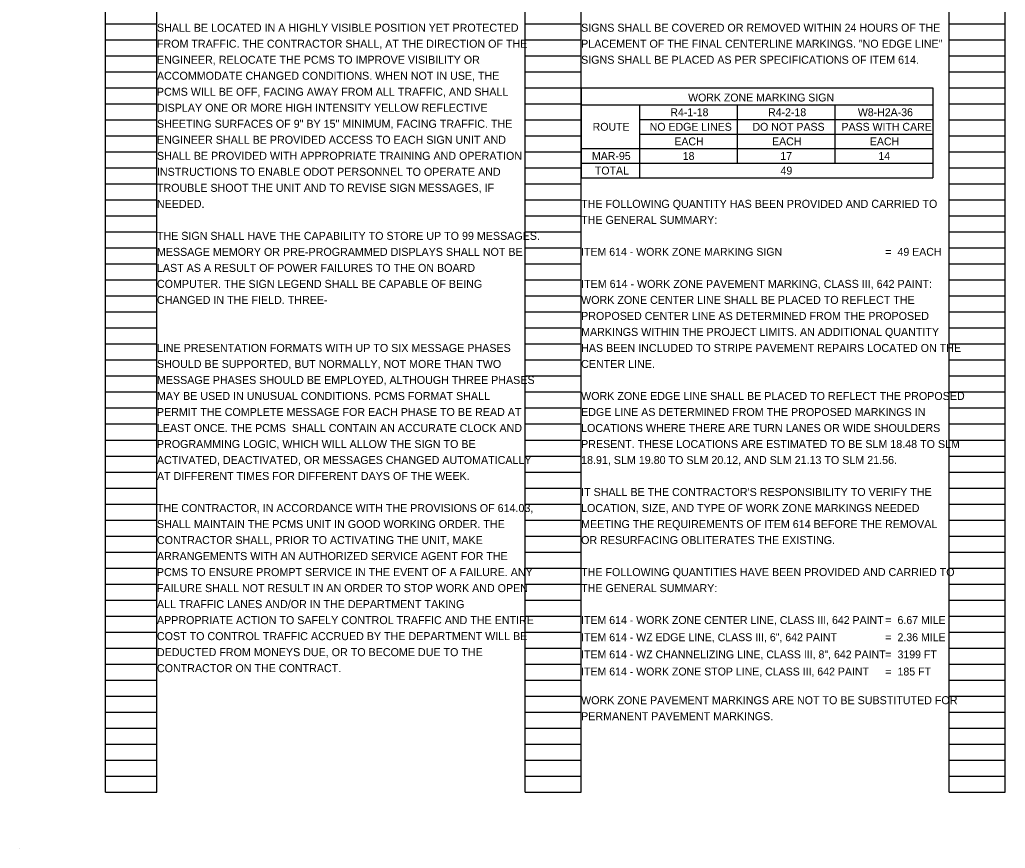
# Model space of a CAD drawing. Extents: x -23 to 32, y -58.1 to 21.1.
# Drawn here: x 0 to 17.24, y -58.15 to -43.65 of the extents above; entities that cross this region are included whole.
import ezdxf

# ---------------------------------------------------------------- set-up
doc = ezdxf.new("R2010")
doc.units = 0
for name, color, linetype in [('Default', 7, 'Continuous'), ('SH_Data', 7, 'Continuous'), ('SH_Text', 7, 'Continuous')]:
    doc.layers.add(name, color=color, linetype=linetype)

msp = doc.modelspace()

# ---------------------------------------------------------------- linework, layer by layer
at = {"layer": 'Default'}
for p, q in [((9.82, -44.845), (15.97, -44.845)), ((9.82, -44.845), (9.82, -46.42)), ((15.97, -44.845), (15.97, -46.42)), ((9.82, -45.145), (15.97, -45.145)), ((10.84, -45.145), (10.84, -46.42)), ((12.55, -45.145), (12.55, -46.165)), ((14.26, -45.145), (14.26, -46.165)), ((10.84, -45.4), (15.97, -45.4)), ((10.84, -45.655), (15.97, -45.655)), ((9.82, -45.91), (15.97, -45.91)), ((9.82, -46.165), (15.97, -46.165)), ((9.82, -46.42), (15.97, -46.42))]:
    msp.add_line(p, q, dxfattribs=at)
at = {"layer": 'SH_Data'}
for p, q in [((1.5, -57.165), (1.5, -37.005)), ((2.4, -57.165), (2.4, -37.005)), ((8.84, -57.165), (8.84, -37.005)), ((9.82, -57.165), (9.82, -37.005)), ((16.26, -57.165), (16.26, -37.005)), ((17.24, -57.165), (17.24, -37.005)), ((1.5, -43.725), (2.4, -43.725)), ((8.84, -43.725), (9.82, -43.725)), ((16.26, -43.725), (17.24, -43.725)), ((1.5, -44.005), (2.4, -44.005)), ((8.84, -44.005), (9.82, -44.005)), ((16.26, -44.005), (17.24, -44.005)), ((1.5, -44.285), (2.4, -44.285)), ((8.84, -44.285), (9.82, -44.285)), ((16.26, -44.285), (17.24, -44.285)), ((1.5, -44.565), (2.4, -44.565)), ((8.84, -44.565), (9.82, -44.565)), ((16.26, -44.565), (17.24, -44.565)), ((1.5, -44.845), (2.4, -44.845)), ((8.84, -44.845), (9.82, -44.845)), ((16.26, -44.845), (17.24, -44.845)), ((1.5, -45.125), (2.4, -45.125)), ((8.84, -45.125), (9.82, -45.125)), ((16.26, -45.125), (17.24, -45.125)), ((1.5, -45.405), (2.4, -45.405)), ((8.84, -45.405), (9.82, -45.405)), ((16.26, -45.405), (17.24, -45.405)), ((1.5, -45.685), (2.4, -45.685)), ((8.84, -45.685), (9.82, -45.685)), ((16.26, -45.685), (17.24, -45.685)), ((1.5, -45.965), (2.4, -45.965)), ((8.84, -45.965), (9.82, -45.965)), ((16.26, -45.965), (17.24, -45.965)), ((1.5, -46.245), (2.4, -46.245)), ((8.84, -46.245), (9.82, -46.245)), ((16.26, -46.245), (17.24, -46.245)), ((1.5, -46.525), (2.4, -46.525)), ((8.84, -46.525), (9.82, -46.525)), ((16.26, -46.525), (17.24, -46.525)), ((1.5, -46.805), (2.4, -46.805)), ((8.84, -46.805), (9.82, -46.805)), ((16.26, -46.805), (17.24, -46.805)), ((1.5, -47.085), (2.4, -47.085)), ((8.84, -47.085), (9.82, -47.085)), ((16.26, -47.085), (17.24, -47.085)), ((1.5, -47.365), (2.4, -47.365)), ((8.84, -47.365), (9.82, -47.365)), ((16.26, -47.365), (17.24, -47.365)), ((1.5, -47.645), (2.4, -47.645)), ((8.84, -47.645), (9.82, -47.645)), ((16.26, -47.645), (17.24, -47.645)), ((1.5, -47.925), (2.4, -47.925)), ((8.84, -47.925), (9.82, -47.925)), ((16.26, -47.925), (17.24, -47.925)), ((1.5, -48.205), (2.4, -48.205)), ((8.84, -48.205), (9.82, -48.205)), ((16.26, -48.205), (17.24, -48.205)), ((1.5, -48.485), (2.4, -48.485)), ((8.84, -48.485), (9.82, -48.485)), ((16.26, -48.485), (17.24, -48.485)), ((1.5, -48.765), (2.4, -48.765)), ((8.84, -48.765), (9.82, -48.765)), ((16.26, -48.765), (17.24, -48.765)), ((1.5, -49.045), (2.4, -49.045)), ((8.84, -49.045), (9.82, -49.045)), ((16.26, -49.045), (17.24, -49.045)), ((1.5, -49.325), (2.4, -49.325)), ((8.84, -49.325), (9.82, -49.325)), ((16.26, -49.325), (17.24, -49.325)), ((1.5, -49.605), (2.4, -49.605)), ((8.84, -49.605), (9.82, -49.605)), ((16.26, -49.605), (17.24, -49.605)), ((1.5, -49.885), (2.4, -49.885)), ((8.84, -49.885), (9.82, -49.885)), ((16.26, -49.885), (17.24, -49.885)), ((1.5, -50.165), (2.4, -50.165)), ((8.84, -50.165), (9.82, -50.165)), ((16.26, -50.165), (17.24, -50.165)), ((1.5, -50.445), (2.4, -50.445)), ((8.84, -50.445), (9.82, -50.445)), ((16.26, -50.445), (17.24, -50.445)), ((1.5, -50.725), (2.4, -50.725)), ((8.84, -50.725), (9.82, -50.725)), ((16.26, -50.725), (17.24, -50.725)), ((1.5, -51.005), (2.4, -51.005)), ((8.84, -51.005), (9.82, -51.005)), ((16.26, -51.005), (17.24, -51.005)), ((1.5, -51.285), (2.4, -51.285)), ((8.84, -51.285), (9.82, -51.285)), ((16.26, -51.285), (17.24, -51.285)), ((1.5, -51.565), (2.4, -51.565)), ((8.84, -51.565), (9.82, -51.565)), ((16.26, -51.565), (17.24, -51.565)), ((1.5, -51.845), (2.4, -51.845)), ((8.84, -51.845), (9.82, -51.845)), ((16.26, -51.845), (17.24, -51.845)), ((1.5, -52.125), (2.4, -52.125)), ((8.84, -52.125), (9.82, -52.125)), ((16.26, -52.125), (17.24, -52.125)), ((1.5, -52.405), (2.4, -52.405)), ((8.84, -52.405), (9.82, -52.405)), ((16.26, -52.405), (17.24, -52.405)), ((1.5, -52.685), (2.4, -52.685)), ((8.84, -52.685), (9.82, -52.685)), ((16.26, -52.685), (17.24, -52.685)), ((1.5, -52.965), (2.4, -52.965)), ((8.84, -52.965), (9.82, -52.965)), ((16.26, -52.965), (17.24, -52.965)), ((1.5, -53.245), (2.4, -53.245)), ((8.84, -53.245), (9.82, -53.245)), ((16.26, -53.245), (17.24, -53.245)), ((1.5, -53.525), (2.4, -53.525)), ((8.84, -53.525), (9.82, -53.525)), ((16.26, -53.525), (17.24, -53.525)), ((1.5, -53.805), (2.4, -53.805)), ((8.84, -53.805), (9.82, -53.805)), ((16.26, -53.805), (17.24, -53.805)), ((1.5, -54.085), (2.4, -54.085)), ((8.84, -54.085), (9.82, -54.085)), ((16.26, -54.085), (17.24, -54.085)), ((1.5, -54.365), (2.4, -54.365)), ((8.84, -54.365), (9.82, -54.365)), ((16.26, -54.365), (17.24, -54.365)), ((1.5, -54.645), (2.4, -54.645)), ((8.84, -54.645), (9.82, -54.645)), ((16.26, -54.645), (17.24, -54.645)), ((1.5, -54.925), (2.4, -54.925)), ((8.84, -54.925), (9.82, -54.925)), ((16.26, -54.925), (17.24, -54.925)), ((1.5, -55.205), (2.4, -55.205)), ((8.84, -55.205), (9.82, -55.205)), ((16.26, -55.205), (17.24, -55.205)), ((1.5, -55.485), (2.4, -55.485)), ((8.84, -55.485), (9.82, -55.485)), ((16.26, -55.485), (17.24, -55.485)), ((1.5, -55.765), (2.4, -55.765)), ((8.84, -55.765), (9.82, -55.765)), ((16.26, -55.765), (17.24, -55.765)), ((1.5, -56.045), (2.4, -56.045)), ((8.84, -56.045), (9.82, -56.045)), ((16.26, -56.045), (17.24, -56.045)), ((1.5, -56.325), (2.4, -56.325)), ((8.84, -56.325), (9.82, -56.325)), ((16.26, -56.325), (17.24, -56.325)), ((1.5, -56.605), (2.4, -56.605)), ((8.84, -56.605), (9.82, -56.605)), ((16.26, -56.605), (17.24, -56.605)), ((1.5, -56.885), (2.4, -56.885)), ((8.84, -56.885), (9.82, -56.885)), ((16.26, -56.885), (17.24, -56.885)), ((1.5, -57.165), (2.4, -57.165)), ((8.84, -57.165), (9.82, -57.165)), ((16.26, -57.165), (17.24, -57.165)), ((0, -58.145), (0, -58.145))]:
    msp.add_line(p, q, dxfattribs=at)

# ---------------------------------------------------------------- texts
at = {"layer": 'Default'}
for s, p in [('WORK ZONE MARKING SIGN', (11.692, -45.085)), ('R4-1-18', (11.381, -45.342)), ('R4-2-18', (13.091, -45.342)), ('W8-H2A-36', (14.661, -45.342)), ('ROUTE', (10.022, -45.597)), ('NO EDGE LINES', (11.02, -45.597)), ('DO NOT PASS', (12.818, -45.597)), ('PASS WITH CARE', (14.375, -45.597)), ('EACH', (11.451, -45.852)), ('EACH', (13.161, -45.852)), ('EACH', (14.871, -45.852)), ('MAR-95', (10.01, -46.107)), ('18', (11.598, -46.107)), ('17', (13.305, -46.107)), ('14', (15.02, -46.107)), ('TOTAL', (10.061, -46.362)), ('49', (13.309, -46.362)), ('ITEM 614 - WORK ZONE MARKING SIGN', (9.82, -47.783)), ('=', (15.141, -47.783)), ('49 EACH', (15.355, -47.783)), ('ITEM 614 - WORK ZONE CENTER LINE, CLASS III, 642 PAINT', (9.82, -54.223)), ('=', (15.141, -54.223)), ('6.67 MILE', (15.355, -54.223)), ('ITEM 614 - WZ EDGE LINE, CLASS III, 6", 642 PAINT', (9.82, -54.523)), ('=', (15.141, -54.523)), ('2.36 MILE', (15.355, -54.523)), ('ITEM 614 - WZ CHANNELIZING LINE, CLASS III, 8", 642 PAINT', (9.82, -54.823)), ('=', (15.141, -54.823)), ('3199 FT', (15.355, -54.823)), ('ITEM 614 - WORK ZONE STOP LINE, CLASS III, 642 PAINT', (9.82, -55.123)), ('185 FT', (15.355, -55.123)), ('=', (15.141, -55.123))]:
    msp.add_text(s, height=0.138, dxfattribs=at).set_placement(p)
at = {"layer": 'SH_Text'}
for s, p in [('SHALL BE LOCATED IN A HIGHLY VISIBLE POSITION YET PROTECTED ', (2.4, -43.865)), ('SIGNS SHALL BE COVERED OR REMOVED WITHIN 24 HOURS OF THE ', (9.82, -43.865)), ('FROM TRAFFIC. THE CONTRACTOR SHALL, AT THE DIRECTION OF THE ', (2.4, -44.145)), ('PLACEMENT OF THE FINAL CENTERLINE MARKINGS. "NO EDGE LINE" ', (9.82, -44.145)), ('ENGINEER, RELOCATE THE PCMS TO IMPROVE VISIBILITY OR ', (2.4, -44.425)), ('SIGNS SHALL BE PLACED AS PER SPECIFICATIONS OF ITEM 614.', (9.82, -44.425)), ('ACCOMMODATE CHANGED CONDITIONS. WHEN NOT IN USE, THE ', (2.4, -44.705)), ('PCMS WILL BE OFF, FACING AWAY FROM ALL TRAFFIC, AND SHALL ', (2.4, -44.985)), ('DISPLAY ONE OR MORE HIGH INTENSITY YELLOW REFLECTIVE ', (2.4, -45.265)), ('SHEETING SURFACES OF 9" BY 15" MINIMUM, FACING TRAFFIC. THE ', (2.4, -45.545)), ('ENGINEER SHALL BE PROVIDED ACCESS TO EACH SIGN UNIT AND ', (2.4, -45.825)), ('SHALL BE PROVIDED WITH APPROPRIATE TRAINING AND OPERATION ', (2.4, -46.105)), ('INSTRUCTIONS TO ENABLE ODOT PERSONNEL TO OPERATE AND ', (2.4, -46.385)), ('TROUBLE SHOOT THE UNIT AND TO REVISE SIGN MESSAGES, IF ', (2.4, -46.665)), ('NEEDED.', (2.4, -46.945)), ('THE FOLLOWING QUANTITY HAS BEEN PROVIDED AND CARRIED TO ', (9.82, -46.945)), ('THE GENERAL SUMMARY:', (9.82, -47.225)), ('THE SIGN SHALL HAVE THE CAPABILITY TO STORE UP TO 99 MESSAGES. ', (2.4, -47.505)), ('MESSAGE MEMORY OR PRE-PROGRAMMED DISPLAYS SHALL NOT BE ', (2.4, -47.785)), ('LAST AS A RESULT OF POWER FAILURES TO THE ON BOARD ', (2.4, -48.065)), ('COMPUTER. THE SIGN LEGEND SHALL BE CAPABLE OF BEING ', (2.4, -48.345)), ('ITEM 614 - WORK ZONE PAVEMENT MARKING, CLASS III, 642 PAINT:', (9.82, -48.345)), ('CHANGED IN THE FIELD. THREE-', (2.4, -48.625)), ('WORK ZONE CENTER LINE SHALL BE PLACED TO REFLECT THE ', (9.82, -48.625)), ('PROPOSED CENTER LINE AS DETERMINED FROM THE PROPOSED ', (9.82, -48.905)), ('MARKINGS WITHIN THE PROJECT LIMITS. AN ADDITIONAL QUANTITY ', (9.82, -49.185)), ('LINE PRESENTATION FORMATS WITH UP TO SIX MESSAGE PHASES ', (2.4, -49.465)), ('HAS BEEN INCLUDED TO STRIPE PAVEMENT REPAIRS LOCATED ON THE ', (9.82, -49.465)), ('SHOULD BE SUPPORTED, BUT NORMALLY, NOT MORE THAN TWO ', (2.4, -49.745)), ('CENTER LINE.', (9.82, -49.745)), ('MESSAGE PHASES SHOULD BE EMPLOYED, ALTHOUGH THREE PHASES ', (2.4, -50.025)), ('MAY BE USED IN UNUSUAL CONDITIONS. PCMS FORMAT SHALL ', (2.4, -50.305)), ('WORK ZONE EDGE LINE SHALL BE PLACED TO REFLECT THE PROPOSED ', (9.82, -50.305)), ('PERMIT THE COMPLETE MESSAGE FOR EACH PHASE TO BE READ AT ', (2.4, -50.585)), ('EDGE LINE AS DETERMINED FROM THE PROPOSED MARKINGS IN ', (9.82, -50.585)), ('LEAST ONCE. THE PCMS  SHALL CONTAIN AN ACCURATE CLOCK AND ', (2.4, -50.865)), ('LOCATIONS WHERE THERE ARE TURN LANES OR WIDE SHOULDERS ', (9.82, -50.865)), ('PROGRAMMING LOGIC, WHICH WILL ALLOW THE SIGN TO BE ', (2.4, -51.145)), ('PRESENT. THESE LOCATIONS ARE ESTIMATED TO BE SLM 18.48 TO SLM ', (9.82, -51.145)), ('ACTIVATED, DEACTIVATED, OR MESSAGES CHANGED AUTOMATICALLY ', (2.4, -51.425)), ('18.91, SLM 19.80 TO SLM 20.12, AND SLM 21.13 TO SLM 21.56.', (9.82, -51.425)), ('AT DIFFERENT TIMES FOR DIFFERENT DAYS OF THE WEEK.', (2.4, -51.705)), ("IT SHALL BE THE CONTRACTOR'S RESPONSIBILITY TO VERIFY THE ", (9.82, -51.985)), ('THE CONTRACTOR, IN ACCORDANCE WITH THE PROVISIONS OF 614.03, ', (2.4, -52.265)), ('LOCATION, SIZE, AND TYPE OF WORK ZONE MARKINGS NEEDED ', (9.82, -52.265)), ('SHALL MAINTAIN THE PCMS UNIT IN GOOD WORKING ORDER. THE ', (2.4, -52.545)), ('MEETING THE REQUIREMENTS OF ITEM 614 BEFORE THE REMOVAL ', (9.82, -52.545)), ('CONTRACTOR SHALL, PRIOR TO ACTIVATING THE UNIT, MAKE ', (2.4, -52.825)), ('OR RESURFACING OBLITERATES THE EXISTING.', (9.82, -52.825)), ('ARRANGEMENTS WITH AN AUTHORIZED SERVICE AGENT FOR THE ', (2.4, -53.105)), ('PCMS TO ENSURE PROMPT SERVICE IN THE EVENT OF A FAILURE. ANY ', (2.4, -53.385)), ('THE FOLLOWING QUANTITIES HAVE BEEN PROVIDED AND CARRIED TO ', (9.82, -53.385)), ('FAILURE SHALL NOT RESULT IN AN ORDER TO STOP WORK AND OPEN ', (2.4, -53.665)), ('THE GENERAL SUMMARY:', (9.82, -53.665)), ('ALL TRAFFIC LANES AND/OR IN THE DEPARTMENT TAKING ', (2.4, -53.945)), ('APPROPRIATE ACTION TO SAFELY CONTROL TRAFFIC AND THE ENTIRE ', (2.4, -54.225)), ('COST TO CONTROL TRAFFIC ACCRUED BY THE DEPARTMENT WILL BE ', (2.4, -54.505)), ('DEDUCTED FROM MONEYS DUE, OR TO BECOME DUE TO THE ', (2.4, -54.785)), ('CONTRACTOR ON THE CONTRACT.', (2.4, -55.065)), ('WORK ZONE PAVEMENT MARKINGS ARE NOT TO BE SUBSTITUTED FOR ', (9.82, -55.625)), ('PERMANENT PAVEMENT MARKINGS.', (9.82, -55.905))]:
    msp.add_text(s, height=0.14, dxfattribs=at).set_placement(p)

doc.saveas('drawing.dxf')
